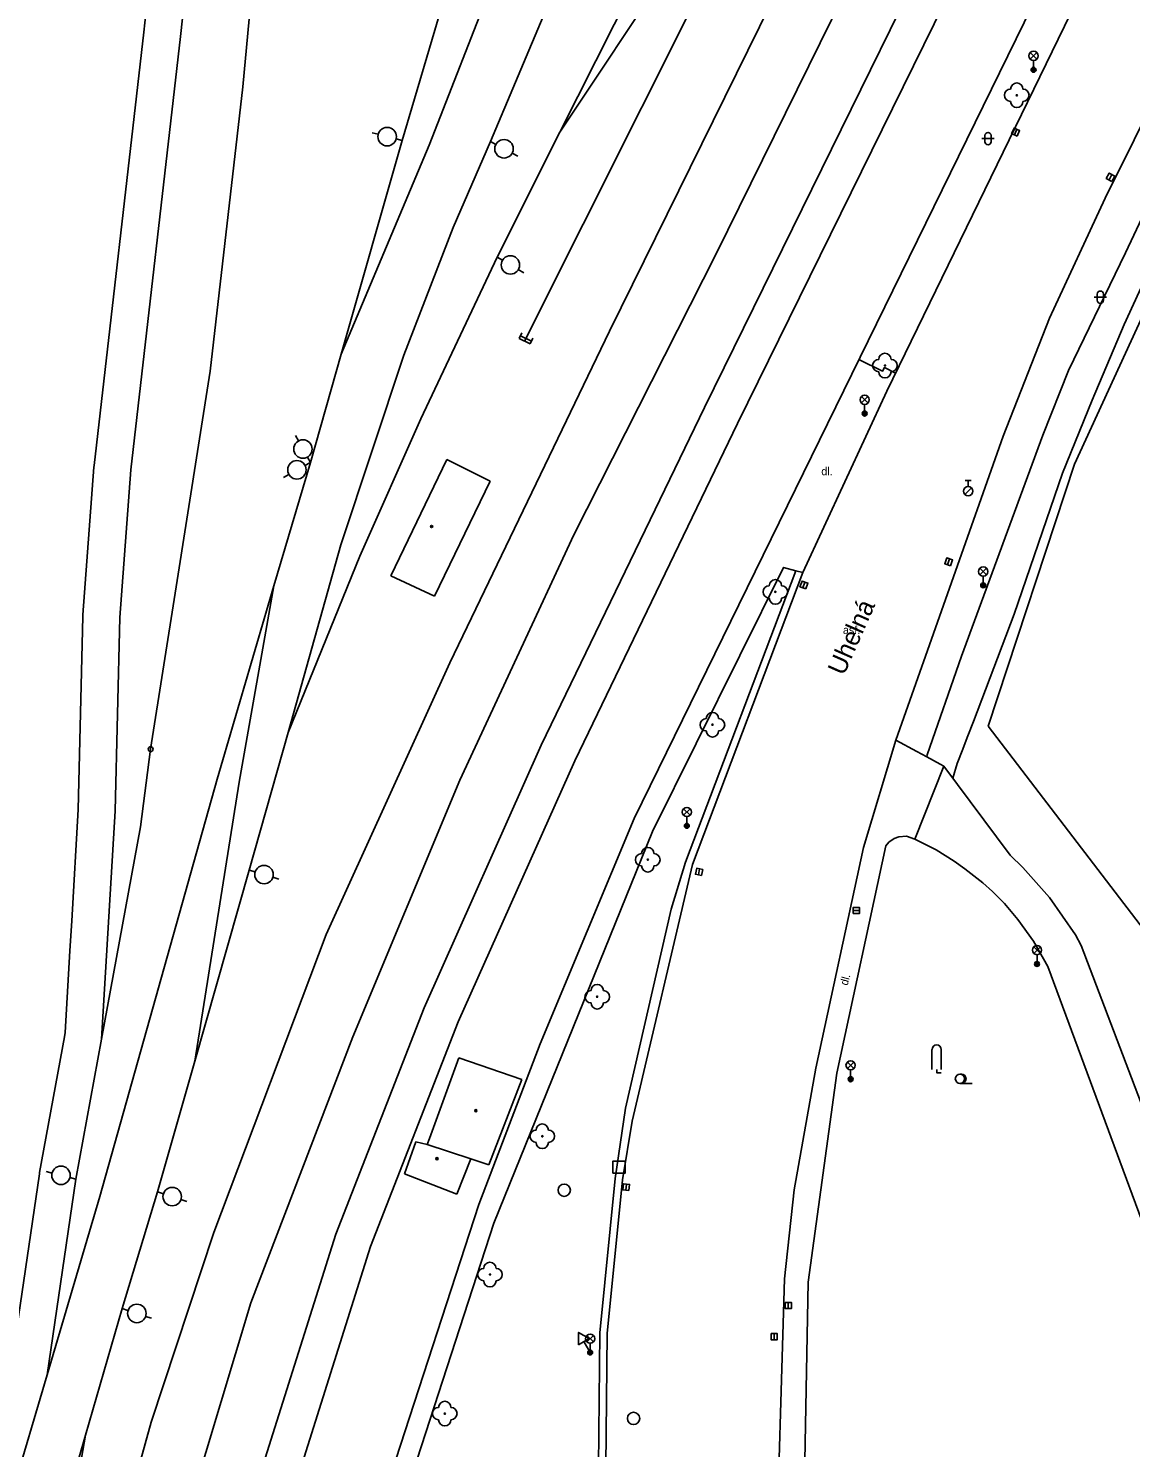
# Model space of a CAD drawing. Extents: x -598932 to -598196, y -1162207 to -1161504.
# Drawn here: x -598333.2 to -598243.7, y -1161932.2 to -1161816.9 of the extents above; entities that cross this region are included whole.
import ezdxf

# ---------------------------------------------------------------- set-up
doc = ezdxf.new("R2010")
doc.units = 0
for name, color, linetype in [('Level 12', 7, 'Continuous'), ('Level 22', 7, 'Continuous'), ('Level 26', 7, 'Continuous'), ('Level 27', 7, 'Continuous'), ('Level 28', 7, 'Continuous'), ('Level 33', 7, 'Continuous'), ('Level 34', 7, 'Continuous'), ('Level 36', 7, 'Continuous'), ('Level 39', 7, 'Continuous'), ('specificka linie pasportu komunikaci', 7, 'Continuous'), ('TM - budovy zdene_ betonove - VP', 7, 'Continuous'), ('TM - CD - osa koleji', 7, 'Continuous'), ('TM - chodniky - VP', 7, 'Continuous'), ('TM - komunikace - VP', 7, 'Continuous'), ('TM - letecke snimky - pomocna linie', 7, 'Continuous'), ('TM - plot dreveny_ kovovy - VP', 7, 'Continuous'), ('TM - popis povrchu', 7, 'Continuous'), ('TM - rozhrani ploch obecne - VP', 7, 'Continuous'), ('TM - zed operna - VP', 7, 'Continuous'), ('ulice', 7, 'Continuous')]:
    doc.layers.add(name, color=color, linetype=linetype)

msp = doc.modelspace()

# ---------------------------------------------------------------- linework, layer by layer
at = {"layer": 'Level 12'}
for p, q in [((-598304.79, -1161825.53), (-598305.28, -1161825.41)), ((-598302.86, -1161826.04), (-598303.34, -1161825.91)), ((-598295.68, -1161826.12), (-598295.24, -1161826.36)), ((-598293.92, -1161827.06), (-598293.47, -1161827.3)), ((-598295.14, -1161835.51), (-598294.71, -1161835.76)), ((-598293.42, -1161836.52), (-598292.98, -1161836.78)), ((-598293.14, -1161841.66), (-598293.36, -1161842.11)), ((-598292.46, -1161842.55), (-598293.36, -1161842.11)), ((-598293.25, -1161841.89), (-598292.35, -1161842.33)), ((-598292.24, -1161842.1), (-598292.46, -1161842.55)), ((-598311.28, -1161850.43), (-598311.52, -1161849.99)), ((-598310.31, -1161852.18), (-598310.75, -1161852.42)), ((-598310.31, -1161852.18), (-598310.55, -1161851.74)), ((-598312.06, -1161853.15), (-598312.5, -1161853.39)), ((-598315.27, -1161885.28), (-598314.79, -1161885.43)), ((-598313.36, -1161885.87), (-598312.88, -1161886.01)), ((-598331.29, -1161909.89), (-598331.77, -1161909.76)), ((-598329.35, -1161910.38), (-598329.83, -1161910.26)), ((-598322.72, -1161911.41), (-598322.24, -1161911.57)), ((-598320.82, -1161912.03), (-598320.34, -1161912.19)), ((-598325.59, -1161920.89), (-598325.12, -1161921.05)), ((-598323.69, -1161921.53), (-598323.22, -1161921.68))]:
    msp.add_line(p, q, dxfattribs=at)
for centre, radius in [((-598304.07, -1161825.72), 0.75), ((-598294.58, -1161826.71), 0.75), ((-598294.06, -1161836.14), 0.75), ((-598310.91, -1161851.09), 0.75), ((-598311.4, -1161852.78), 0.75), ((-598323.28, -1161875.46), 0.2), ((-598314.07, -1161885.65), 0.75), ((-598330.56, -1161910.07), 0.75), ((-598321.53, -1161911.8), 0.75), ((-598324.4, -1161921.29), 0.75)]:
    msp.add_circle(centre, radius, dxfattribs=at)
at = {"layer": 'Level 22'}
for centre in [(-598252.93, -1161822.36), (-598263.64, -1161844.31), (-598272.54, -1161862.69), (-598277.65, -1161873.48), (-598282.9, -1161884.44), (-598287.01, -1161895.57), (-598291.47, -1161906.9), (-598295.72, -1161918.13), (-598299.39, -1161929.42)]:
    msp.add_circle(centre, 0.05, dxfattribs=at)
for centre, start, end in [((-598252.93, -1161821.86), 0, 180), ((-598253.43, -1161822.36), 90, 270), ((-598252.93, -1161822.86), 180, 0), ((-598252.43, -1161822.36), 270, 90), ((-598263.64, -1161843.81), 0, 180), ((-598264.14, -1161844.31), 90, 270), ((-598263.64, -1161844.81), 180, 0), ((-598263.14, -1161844.31), 270, 90), ((-598272.54, -1161862.19), 0, 180), ((-598273.04, -1161862.69), 90, 270), ((-598272.54, -1161863.19), 180, 0), ((-598272.04, -1161862.69), 270, 90), ((-598278.15, -1161873.48), 90, 270), ((-598277.65, -1161872.98), 0, 180), ((-598277.15, -1161873.48), 270, 90), ((-598277.65, -1161873.98), 180, 0), ((-598283.4, -1161884.44), 90, 270), ((-598282.9, -1161883.94), 0, 180), ((-598282.4, -1161884.44), 270, 90), ((-598282.9, -1161884.94), 180, 0), ((-598287.51, -1161895.57), 90, 270), ((-598287.01, -1161895.07), 0, 180), ((-598286.51, -1161895.57), 270, 90), ((-598287.01, -1161896.07), 180, 0), ((-598291.97, -1161906.9), 90, 270), ((-598291.47, -1161906.4), 0, 180), ((-598290.97, -1161906.9), 270, 90), ((-598291.47, -1161907.4), 180, 0), ((-598295.72, -1161917.63), 0, 180), ((-598296.22, -1161918.13), 90, 270), ((-598295.22, -1161918.13), 270, 90), ((-598295.72, -1161918.63), 180, 0), ((-598299.89, -1161929.42), 90, 270), ((-598299.39, -1161928.92), 0, 180), ((-598298.89, -1161929.42), 270, 90), ((-598299.39, -1161929.92), 180, 0)]:
    msp.add_arc(centre, 0.5, start, end, dxfattribs=at)
at = {"layer": 'Level 26'}
msp.add_lwpolyline([(-598285.74, -1161909.91), (-598284.74, -1161909.91), (-598284.74, -1161908.91), (-598285.74, -1161908.91)], close=True, dxfattribs=at)
at = {"layer": 'Level 27'}
for p, q in [((-598253.13, -1161825.58), (-598252.93, -1161825.12)), ((-598245.44, -1161829.24), (-598245.2, -1161828.8)), ((-598258.55, -1161860.49), (-598258.39, -1161860.01)), ((-598270.3, -1161862.37), (-598270.14, -1161861.89)), ((-598278.79, -1161885.67), (-598278.69, -1161885.19)), ((-598266.22, -1161888.57), (-598265.72, -1161888.57)), ((-598284.69, -1161911.28), (-598284.63, -1161910.78)), ((-598271.49, -1161920.4), (-598271.49, -1161920.9)), ((-598272.64, -1161922.93), (-598272.64, -1161923.43))]:
    msp.add_line(p, q, dxfattribs=at)
for points in [[(-598252.91, -1161825.68), (-598252.7, -1161825.23), (-598253.15, -1161825.02), (-598253.36, -1161825.47)], [(-598245.22, -1161829.36), (-598244.98, -1161828.92), (-598245.42, -1161828.68), (-598245.66, -1161829.12)], [(-598258.32, -1161860.57), (-598258.15, -1161860.1), (-598258.62, -1161859.93), (-598258.79, -1161860.4)], [(-598270.07, -1161862.45), (-598269.9, -1161861.98), (-598270.37, -1161861.81), (-598270.54, -1161862.28)], [(-598278.55, -1161885.73), (-598278.44, -1161885.24), (-598278.93, -1161885.13), (-598279.04, -1161885.62)], [(-598266.22, -1161888.82), (-598265.72, -1161888.82), (-598265.72, -1161888.32), (-598266.22, -1161888.32)], [(-598284.44, -1161911.31), (-598284.38, -1161910.81), (-598284.88, -1161910.75), (-598284.94, -1161911.25)], [(-598271.74, -1161920.4), (-598271.74, -1161920.9), (-598271.24, -1161920.9), (-598271.24, -1161920.4)], [(-598272.89, -1161922.93), (-598272.89, -1161923.43), (-598272.39, -1161923.43), (-598272.39, -1161922.93)]]:
    msp.add_lwpolyline(points, close=True, dxfattribs=at)
for centre in [(-598289.69, -1161911.28), (-598284.06, -1161929.81)]:
    msp.add_circle(centre, 0.5, dxfattribs=at)
at = {"layer": 'Level 28'}
for p, q in [((-598257.13, -1161853.64), (-598256.63, -1161853.64)), ((-598256.88, -1161854.14), (-598256.88, -1161853.64)), ((-598257.14, -1161854.78), (-598256.61, -1161854.25))]:
    msp.add_line(p, q, dxfattribs=at)
msp.add_circle((-598256.88, -1161854.51), 0.375, dxfattribs=at)
at = {"layer": 'Level 33'}
for p, q in [((-598251.84, -1161819.43), (-598251.31, -1161818.9)), ((-598251.84, -1161818.9), (-598251.31, -1161819.43)), ((-598251.57, -1161819.54), (-598251.57, -1161820.29)), ((-598265.55, -1161847.35), (-598265.02, -1161846.82)), ((-598265.55, -1161846.82), (-598265.02, -1161847.35)), ((-598265.29, -1161847.46), (-598265.29, -1161848.21)), ((-598255.93, -1161861.3), (-598255.4, -1161860.77)), ((-598255.93, -1161860.77), (-598255.4, -1161861.3)), ((-598255.66, -1161861.41), (-598255.66, -1161862.16)), ((-598280, -1161880.83), (-598279.47, -1161880.3)), ((-598280, -1161880.3), (-598279.47, -1161880.83)), ((-598279.73, -1161880.94), (-598279.73, -1161881.69)), ((-598251.55, -1161892.05), (-598251.02, -1161891.52)), ((-598251.55, -1161891.52), (-598251.02, -1161892.05)), ((-598251.29, -1161892.16), (-598251.29, -1161892.91)), ((-598266.69, -1161901.41), (-598266.16, -1161900.88)), ((-598266.69, -1161900.88), (-598266.16, -1161901.41)), ((-598266.43, -1161901.52), (-598266.43, -1161902.27)), ((-598287.84, -1161923.6), (-598287.31, -1161923.07)), ((-598287.84, -1161923.07), (-598287.31, -1161923.6)), ((-598287.58, -1161923.71), (-598287.58, -1161924.46))]:
    msp.add_line(p, q, dxfattribs=at)
for centre, radius in [((-598251.57, -1161819.16), 0.375), ((-598251.57, -1161820.29), 0.2), ((-598251.57, -1161820.29), 0.145), ((-598251.57, -1161820.29), 0.0876), ((-598265.29, -1161847.09), 0.375), ((-598265.29, -1161848.21), 0.2), ((-598265.29, -1161848.21), 0.145), ((-598265.29, -1161848.21), 0.0876), ((-598255.66, -1161861.04), 0.375), ((-598255.66, -1161862.16), 0.2), ((-598255.66, -1161862.16), 0.145), ((-598255.66, -1161862.16), 0.0876), ((-598279.73, -1161880.57), 0.375), ((-598279.73, -1161881.69), 0.2), ((-598279.73, -1161881.69), 0.145), ((-598279.73, -1161881.69), 0.0876), ((-598251.29, -1161891.78), 0.375), ((-598251.29, -1161892.91), 0.2), ((-598251.29, -1161892.91), 0.145), ((-598251.29, -1161892.91), 0.0876), ((-598266.43, -1161901.14), 0.375), ((-598266.43, -1161902.27), 0.2), ((-598266.43, -1161902.27), 0.145), ((-598266.43, -1161902.27), 0.0876), ((-598287.58, -1161923.34), 0.375), ((-598287.58, -1161924.46), 0.2), ((-598287.58, -1161924.46), 0.145), ((-598287.58, -1161924.46), 0.0876)]:
    msp.add_circle(centre, radius, dxfattribs=at)
at = {"layer": 'Level 34'}
for p, q in [((-598288.09, -1161923.58), (-598287.58, -1161924.46)), ((-598287.8, -1161924.59), (-598287.36, -1161924.34))]:
    msp.add_line(p, q, dxfattribs=at)
msp.add_lwpolyline([(-598288.52, -1161923.83), (-598287.66, -1161923.33), (-598288.52, -1161922.83)], close=True, dxfattribs=at)
at = {"layer": 'Level 36'}
for p, q in [((-598255.77, -1161825.88), (-598254.77, -1161825.88)), ((-598255.52, -1161825.63), (-598255.52, -1161826.13)), ((-598255.02, -1161825.63), (-598255.02, -1161826.13)), ((-598246.65, -1161838.76), (-598245.65, -1161838.76)), ((-598246.4, -1161838.51), (-598246.4, -1161839.01)), ((-598245.9, -1161838.51), (-598245.9, -1161839.01)), ((-598259.82, -1161899.86), (-598259.82, -1161901.49)), ((-598259.07, -1161899.86), (-598259.07, -1161901.49)), ((-598257.55, -1161902.61), (-598256.55, -1161902.61))]:
    msp.add_line(p, q, dxfattribs=at)
msp.add_lwpolyline([(-598259.44, -1161901.49), (-598259.44, -1161901.74), (-598259.07, -1161901.74)], dxfattribs=at)
msp.add_circle((-598257.55, -1161902.23), 0.375, dxfattribs=at)
for centre, radius, start, end in [((-598255.27, -1161825.63), 0.25, 0, 180), ((-598255.27, -1161826.13), 0.25, 180, 0), ((-598246.15, -1161838.51), 0.25, 0, 180), ((-598246.15, -1161839.01), 0.25, 180, 0), ((-598259.44, -1161899.86), 0.375, 0, 180), ((-598257.43, -1161902.23), 0.375, 260.4059, 99.5941)]:
    msp.add_arc(centre, radius, start, end, dxfattribs=at)
at = {"layer": 'Level 39'}
for centre, radius in [((-598300.46, -1161857.38), 0.09), ((-598300.46, -1161857.38), 0.0398), ((-598296.87, -1161904.83), 0.09), ((-598296.87, -1161904.83), 0.0398), ((-598300.03, -1161908.72), 0.09), ((-598300.03, -1161908.72), 0.0398)]:
    msp.add_circle(centre, radius, dxfattribs=at)
at = {"layer": 'specificka linie pasportu komunikaci'}
for points in [[(-598260.25, -1161876.09), (-598260.2, -1161875.92), (-598257.41, -1161867.9), (-598250.82, -1161849.97), (-598248.72, -1161844.7), (-598244.1, -1161835.15), (-598237.16, -1161820.46), (-598241.17, -1161821.58), (-598241.24, -1161821.6)], [(-598234.42, -1161819.83), (-598239.97, -1161831.72), (-598244.22, -1161840.97), (-598246.81, -1161847.13), (-598249.22, -1161853.05), (-598253.15, -1161864.51), (-598256.46, -1161873.22)], [(-598262.78, -1161844.93), (-598262.78, -1161844.93), (-598263.69, -1161844.47), (-598263.84, -1161844.77), (-598265.75, -1161843.83)], [(-598256.46, -1161873.22), (-598256.91, -1161874.39), (-598257.04, -1161874.74), (-598257.32, -1161875.47), (-598257.77, -1161876.62)], [(-598257.77, -1161876.62), (-598258.12, -1161877.82)], [(-598281, -1161888.45), (-598279.84, -1161884.65)], [(-598284.7, -1161904.61), (-598281, -1161888.45)]]:
    msp.add_lwpolyline(points, dxfattribs=at)
at = {"layer": 'TM - budovy zdene_ betonove - VP'}
for points in [[(-598303.76, -1161861.39), (-598299.23, -1161851.93)], [(-598299.23, -1161851.93), (-598295.71, -1161853.69)], [(-598295.71, -1161853.69), (-598300.22, -1161863.05)], [(-598300.22, -1161863.05), (-598303.76, -1161861.39)], [(-598300.64, -1161907.08), (-598298.26, -1161900.52)], [(-598298.26, -1161900.52), (-598293.13, -1161902.29)], [(-598293.13, -1161902.29), (-598295.82, -1161909.22)], [(-598302.67, -1161909.95), (-598301.75, -1161907.34)], [(-598301.75, -1161907.34), (-598300.83, -1161907.58)], [(-598300.83, -1161907.58), (-598300.64, -1161907.08)], [(-598300.83, -1161907.58), (-598297.28, -1161908.74)], [(-598297.28, -1161908.74), (-598298.4, -1161911.61)], [(-598295.82, -1161909.22), (-598297.28, -1161908.74)], [(-598298.4, -1161911.61), (-598302.67, -1161909.95)]]:
    msp.add_lwpolyline(points, dxfattribs=at)
at = {"layer": 'TM - CD - osa koleji'}
for points in [[(-598315.41, -1161767.58), (-598320.86, -1161817.58), (-598324.9, -1161852.77), (-598325.79, -1161864.77), (-598326.17, -1161880.48)], [(-598318.45, -1161844.78), (-598315.78, -1161821.69), (-598311.86, -1161779.52), (-598310.47, -1161767.81)], [(-598310.31, -1161852.18), (-598307.8, -1161843.38), (-598302.86, -1161826.04), (-598299.64, -1161815.15), (-598294.44, -1161797.56), (-598287.03, -1161771.17)], [(-598279.66, -1161774.81), (-598281.63, -1161778.87), (-598284.25, -1161785.34), (-598290.86, -1161801.71), (-598295.43, -1161813.02), (-598300.65, -1161826.42)], [(-598315.27, -1161885.28), (-598312.12, -1161874.12), (-598307.82, -1161858.87), (-598302.71, -1161843.47), (-598298.71, -1161833.11), (-598295.68, -1161826.12), (-598291.17, -1161815.46), (-598285.2, -1161801.33), (-598274.71, -1161777.25)], [(-598267.73, -1161780.7), (-598282.72, -1161810.8), (-598290.04, -1161825.36), (-598295.14, -1161835.51), (-598301.33, -1161848.65), (-598306.3, -1161859.78)], [(-598262.97, -1161783.05), (-598266.99, -1161790.88), (-598273.89, -1161804.34), (-598292.91, -1161842.33)], [(-598330.7, -1161957.12), (-598323.25, -1161930.13), (-598318.14, -1161914.72), (-598309.03, -1161890.52), (-598298.97, -1161868.44), (-598286, -1161841.52), (-598259.79, -1161788.26), (-598258.34, -1161785.34)], [(-598253.85, -1161787.55), (-598277.35, -1161835.24), (-598288.92, -1161858.05), (-598298.17, -1161877.98), (-598306.86, -1161898.82), (-598315.14, -1161920.44), (-598321.21, -1161940.59), (-598327.42, -1161961.55), (-598336.66, -1161994.53)], [(-598332.49, -1161997.92), (-598324.93, -1161971.61), (-598314.3, -1161934.07), (-598308.24, -1161914.84), (-598301.06, -1161896.46), (-598291.55, -1161875.15), (-598278.3, -1161847.71), (-598249.73, -1161789.59)], [(-598290.04, -1161825.36), (-598281.04, -1161811.79), (-598266.99, -1161790.88)], [(-598300.65, -1161826.42), (-598307.8, -1161843.38)], [(-598323.28, -1161875.46), (-598321.2, -1161862.29), (-598318.45, -1161844.78)], [(-598310.31, -1161852.18), (-598313.27, -1161862.21), (-598317.89, -1161877.89)], [(-598306.3, -1161859.78), (-598312.12, -1161874.12)], [(-598313.27, -1161862.21), (-598316.1, -1161878.15)], [(-598323.28, -1161875.46), (-598324.1, -1161881.77)], [(-598317.89, -1161877.89), (-598327.42, -1161911.8)], [(-598319.7, -1161900.79), (-598316.1, -1161878.15)], [(-598327.26, -1161899.01), (-598326.17, -1161880.48)], [(-598329.35, -1161910.38), (-598327.26, -1161899.01), (-598324.1, -1161881.77)], [(-598315.27, -1161885.28), (-598319.7, -1161900.79), (-598322.72, -1161911.41)], [(-598331.69, -1161926.28), (-598329.35, -1161910.38)], [(-598344.63, -1161988.07), (-598339.52, -1161970.16), (-598333.18, -1161947.17), (-598328.56, -1161931.17), (-598325.59, -1161920.89), (-598322.72, -1161911.41)], [(-598327.42, -1161911.8), (-598331.69, -1161926.28), (-598334.58, -1161936.08), (-598336.84, -1161944.95), (-598341.23, -1161962.18)], [(-598328.56, -1161931.17), (-598331.39, -1161947.33), (-598332.63, -1161956.86)]]:
    msp.add_lwpolyline(points, dxfattribs=at)
at = {"layer": 'TM - chodniky - VP'}
for points in [[(-598321.47, -1161998.94), (-598319.2, -1161991.02), (-598315.42, -1161976.86), (-598309.25, -1161956.54), (-598295.42, -1161913.97), (-598282.51, -1161882.14), (-598271.87, -1161860.71), (-598270.88, -1161860.98)], [(-598270.88, -1161860.98), (-598270.3, -1161861.13)], [(-598262.77, -1161874.74), (-598261.06, -1161875.66), (-598260.25, -1161876.09), (-598259.15, -1161876.68), (-598258.85, -1161876.84)], [(-598258.85, -1161876.84), (-598253.47, -1161884.08)], [(-598261.21, -1161882.77), (-598261.9, -1161882.53), (-598262.5, -1161882.59), (-598262.89, -1161882.72), (-598263.32, -1161883.01), (-598263.57, -1161883.32)], [(-598250.4, -1161893.11), (-598251.57, -1161891.06), (-598252.84, -1161889.29), (-598253.92, -1161888), (-598254.91, -1161887.01), (-598255.69, -1161886.33), (-598257.15, -1161885.18), (-598258.03, -1161884.55), (-598259.48, -1161883.65), (-598261.21, -1161882.77)], [(-598267.56, -1161901.78), (-598263.57, -1161883.32)], [(-598247.7, -1161891.4), (-598248.16, -1161890.54), (-598250.28, -1161887.5), (-598252.44, -1161885.07), (-598253.47, -1161884.08)], [(-598247.7, -1161891.4), (-598233.67, -1161928.29)], [(-598250.4, -1161893.11), (-598237.18, -1161928.9)], [(-598269.89, -1161918.74), (-598267.56, -1161901.78)], [(-598270.34, -1161943.41), (-598269.89, -1161918.74)]]:
    msp.add_lwpolyline(points, dxfattribs=at)
at = {"layer": 'TM - komunikace - VP'}
for points in [[(-598240.61, -1161799.32), (-598244.6, -1161807.54), (-598263.48, -1161846.38)], [(-598236.37, -1161811.8), (-598245.76, -1161830.72)], [(-598245.76, -1161830.72), (-598250.27, -1161840.47), (-598254.03, -1161850.05), (-598262.77, -1161874.74)], [(-598263.48, -1161846.38), (-598270.3, -1161861.13)], [(-598270.3, -1161861.13), (-598279.26, -1161884.82)], [(-598262.77, -1161874.74), (-598265.38, -1161883.44), (-598269.26, -1161901.36), (-598271.02, -1161911.25), (-598271.81, -1161918.47), (-598272.52, -1161943.07), (-598272.06, -1161955.75), (-598271.25, -1161967.2), (-598270.31, -1161978.85)], [(-598284.95, -1161910.44), (-598286.19, -1161922.91)], [(-598286.19, -1161922.91), (-598286.42, -1161944.5)]]:
    msp.add_lwpolyline(points, dxfattribs=at)
at = {"layer": 'TM - letecke snimky - pomocna linie'}
for points in [[(-598345.39, -1161932), (-598345.23, -1161933.17), (-598341.9, -1161949.98), (-598339.75, -1161944.21), (-598339.66, -1161943.91), (-598337.49, -1161935.34), (-598337.46, -1161935.23), (-598334.67, -1161925.84), (-598334.58, -1161925.43), (-598332.32, -1161909.94), (-598332.3, -1161909.85), (-598330.27, -1161898.83), (-598330.22, -1161898.47), (-598329.83, -1161891.84), (-598329.69, -1161889.41), (-598329.17, -1161880.36), (-598328.79, -1161864.7), (-598328.78, -1161864.55), (-598327.89, -1161852.55), (-598327.88, -1161852.43), (-598323.84, -1161817.24), (-598322.85, -1161808.11), (-598322.82, -1161807.86), (-598319.23, -1161762.27)], [(-598247.39, -1161791.37), (-598249.58, -1161796.08), (-598275.61, -1161849.03), (-598288.83, -1161876.41), (-598298.29, -1161897.62), (-598305.41, -1161915.84), (-598311.43, -1161934.93), (-598312.26, -1161937.86), (-598312.21, -1161937.71), (-598322.05, -1161972.43), (-598326.74, -1161988.76), (-598328.41, -1161995.16)], [(-598284.95, -1161910.44), (-598284.18, -1161905.67), (-598279.26, -1161884.82)], [(-598284.7, -1161904.61), (-598285.55, -1161910.34)]]:
    msp.add_lwpolyline(points, dxfattribs=at)
at = {"layer": 'TM - plot dreveny_ kovovy - VP'}
for points in [[(-598248.25, -1161852.32), (-598234.14, -1161821.62)], [(-598255.25, -1161873.61), (-598248.25, -1161852.32)], [(-598195.56, -1161951.61), (-598255.25, -1161873.61)]]:
    msp.add_lwpolyline(points, dxfattribs=at)
at = {"layer": 'TM - rozhrani ploch obecne - VP'}
for points in [[(-598270.88, -1161860.98), (-598279.84, -1161884.65)], [(-598261.21, -1161882.77), (-598258.85, -1161876.84)], [(-598285.55, -1161910.34), (-598286.79, -1161922.87)], [(-598286.79, -1161922.87), (-598287.02, -1161944.53)]]:
    msp.add_lwpolyline(points, dxfattribs=at)
at = {"layer": 'TM - zed operna - VP'}
for points in [[(-598266.32, -1161845), (-598244.31, -1161800.07)], [(-598296.63, -1161912.44), (-598291.65, -1161899.4), (-598284, -1161881.09), (-598266.32, -1161845)], [(-598322.49, -1161996.51), (-598310.87, -1161956.18), (-598296.63, -1161912.44)]]:
    msp.add_lwpolyline(points, dxfattribs=at)

# ---------------------------------------------------------------- texts
at = {"layer": 'TM - popis povrchu'}
for s, p in [('dl.', (-598268.81, -1161853.22)), ('asf.', (-598267.05, -1161866.11))]:
    msp.add_text(s, height=0.65, dxfattribs=at).set_placement(p)
msp.add_text('dl.', height=0.65, rotation=74.87, dxfattribs=at).set_placement((-598266.68, -1161894.7))
at = {"layer": 'ulice'}
msp.add_text('Uhelná', height=1.5, rotation=66.1706, dxfattribs=at).set_placement((-598266.98, -1161869.56))

doc.saveas('drawing.dxf')
